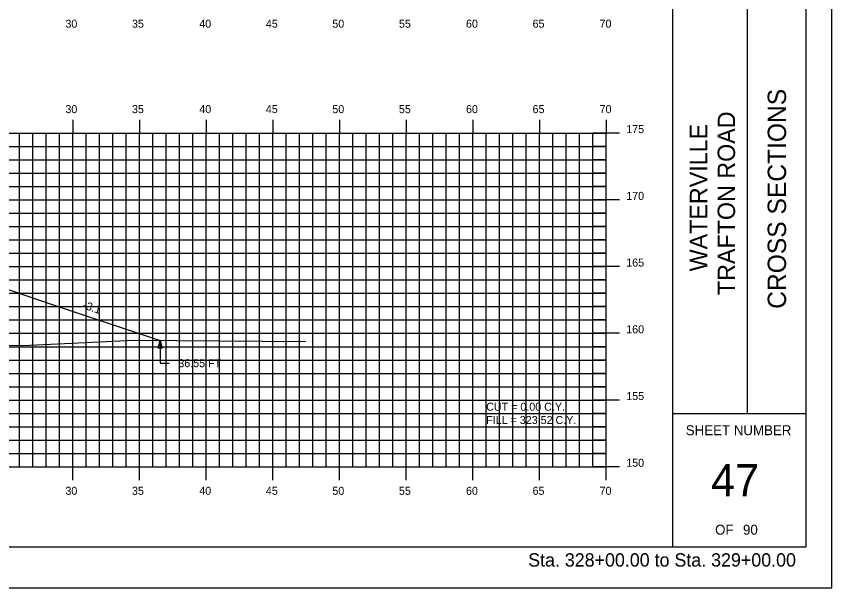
# Model space of a CAD drawing. Extents: x 1140981 to 1141151, y 608981 to 609091.
# Drawn here: x 1141089.5 to 1141150.7, y 608981.3 to 609024.1 of the extents above; entities that cross this region are included whole.
import ezdxf

# ---------------------------------------------------------------- set-up
doc = ezdxf.new("R2010")
doc.units = 0
for name, color, linetype in [('ANNOTATION', 7, 'Continuous'), ('BORDER', 7, 'Continuous'), ('D_Roadway_SlopeLines', 7, 'Continuous'), ('D_Text_Standard', 7, 'Continuous'), ('H_V ANNOTATION', 7, 'Continuous'), ('HIGHWAY_TITLE', 7, 'Continuous'), ('MAJOR', 7, 'Continuous'), ('MINOR', 7, 'Continuous'), ('PLOT BOUNDARY', 7, 'Continuous'), ('S_Roadway_Centerline', 7, 'Continuous')]:
    doc.layers.add(name, color=color, linetype=linetype)

msp = doc.modelspace()

# ---------------------------------------------------------------- linework, layer by layer
msp.add_lwpolyline([(1141028.37, 608999.408), (1141037.741, 609002.532), (1141040.741, 609003.532), (1141048.445, 609006.1), (1141048.446, 609006.1), (1141052.758, 609006.272), (1141063.758, 609006.492), (1141074.758, 609006.272), (1141081.758, 609005.992), (1141089.29, 609003.482), (1141092.29, 609002.482), (1141100.308, 608999.809)])
at = {"layer": 'BORDER'}
for p, q in [((1141138.758, 608984.335), (1141138.758, 609089.335)), ((1141144.349, 608994.338), (1141144.349, 609029.338)), ((1141138.758, 608994.338), (1141148.758, 608994.338))]:
    msp.add_line(p, q, dxfattribs=at)
msp.add_lwpolyline([(1140988.758, 608984.335), (1141148.758, 608984.335), (1141148.758, 609089.335), (1140988.758, 609089.335)], close=True, dxfattribs=at)
at = {"layer": 'D_Roadway_SlopeLines'}
for points in [[(1141089.29, 609003.482), (1141092.29, 609002.482)], [(1141092.29, 609002.482), (1141100.308, 608999.809)]]:
    msp.add_lwpolyline(points, dxfattribs=at)
at = {"layer": 'D_Text_Standard'}
msp.add_lwpolyline([(1141100.308, 608999.809), (1141100.455, 608999.227), (1141100.164, 608999.226)], close=True, dxfattribs=at)
msp.add_lwpolyline([(1141100.308, 608999.809), (1141100.312, 608998.097), (1141100.992, 608998.097)], dxfattribs=at)
at = {"layer": 'MAJOR'}
for p, q in [((1141093.758, 609016.337), (1141093.758, 609015.335)), ((1141098.758, 609016.337), (1141098.758, 609015.335)), ((1141103.758, 609016.337), (1141103.758, 609015.335)), ((1141108.758, 609016.337), (1141108.758, 609015.335)), ((1141113.758, 609016.337), (1141113.758, 609015.335)), ((1141118.758, 609016.337), (1141118.758, 609015.335)), ((1141123.758, 609016.337), (1141123.758, 609015.335)), ((1141128.758, 609016.337), (1141128.758, 609015.335)), ((1141133.758, 609016.337), (1141133.758, 609015.335)), ((1140993.758, 609015.335), (1141133.758, 609015.335)), ((1140993.758, 609015.335), (1141133.758, 609015.335)), ((1141093.758, 608990.335), (1141093.758, 609015.335)), ((1141098.758, 608990.335), (1141098.758, 609015.335)), ((1141103.758, 608990.335), (1141103.758, 609015.335)), ((1141108.758, 608990.335), (1141108.758, 609015.335)), ((1141113.758, 608990.335), (1141113.758, 609015.335)), ((1141118.758, 608990.335), (1141118.758, 609015.335)), ((1141123.758, 608990.335), (1141123.758, 609015.335)), ((1141128.758, 608990.335), (1141128.758, 609015.335)), ((1141134.76, 609015.335), (1141132.756, 609015.335)), ((1141133.758, 608990.335), (1141133.758, 609015.335)), ((1141133.758, 608990.335), (1141133.758, 609015.335)), ((1140993.758, 609010.335), (1141133.758, 609010.335)), ((1141134.76, 609010.335), (1141132.756, 609010.335)), ((1140993.758, 609005.335), (1141133.758, 609005.335)), ((1141134.76, 609005.335), (1141132.756, 609005.335)), ((1140993.758, 609000.335), (1141133.758, 609000.335)), ((1141134.76, 609000.335), (1141132.756, 609000.335)), ((1140993.758, 608995.335), (1141133.758, 608995.335)), ((1141134.76, 608995.335), (1141132.756, 608995.335)), ((1140993.758, 608990.335), (1141133.758, 608990.335)), ((1140993.758, 608990.335), (1141133.758, 608990.335)), ((1141093.758, 608989.333), (1141093.758, 608990.335)), ((1141098.758, 608989.333), (1141098.758, 608990.335)), ((1141103.758, 608989.333), (1141103.758, 608990.335)), ((1141108.758, 608989.333), (1141108.758, 608990.335)), ((1141113.758, 608989.333), (1141113.758, 608990.335)), ((1141118.758, 608989.333), (1141118.758, 608990.335)), ((1141123.758, 608989.333), (1141123.758, 608990.335)), ((1141128.758, 608989.333), (1141128.758, 608990.335)), ((1141134.76, 608990.335), (1141132.756, 608990.335)), ((1141133.758, 608989.333), (1141133.758, 608990.335))]:
    msp.add_line(p, q, dxfattribs=at)
at = {"layer": 'MINOR'}
for p, q in [((1141089.758, 608990.335), (1141089.758, 609015.335)), ((1141090.758, 608990.335), (1141090.758, 609015.335)), ((1141091.758, 608990.335), (1141091.758, 609015.335)), ((1141092.758, 608990.335), (1141092.758, 609015.335)), ((1141094.758, 608990.335), (1141094.758, 609015.335)), ((1141095.758, 608990.335), (1141095.758, 609015.335)), ((1141096.758, 608990.335), (1141096.758, 609015.335)), ((1141097.758, 608990.335), (1141097.758, 609015.335)), ((1141099.758, 608990.335), (1141099.758, 609015.335)), ((1141100.758, 608990.335), (1141100.758, 609015.335)), ((1141101.758, 608990.335), (1141101.758, 609015.335)), ((1141102.758, 608990.335), (1141102.758, 609015.335)), ((1141104.758, 608990.335), (1141104.758, 609015.335)), ((1141105.758, 608990.335), (1141105.758, 609015.335)), ((1141106.758, 608990.335), (1141106.758, 609015.335)), ((1141107.758, 608990.335), (1141107.758, 609015.335)), ((1141109.758, 608990.335), (1141109.758, 609015.335)), ((1141110.758, 608990.335), (1141110.758, 609015.335)), ((1141111.758, 608990.335), (1141111.758, 609015.335)), ((1141112.758, 608990.335), (1141112.758, 609015.335)), ((1141114.758, 608990.335), (1141114.758, 609015.335)), ((1141115.758, 608990.335), (1141115.758, 609015.335)), ((1141116.758, 608990.335), (1141116.758, 609015.335)), ((1141117.758, 608990.335), (1141117.758, 609015.335)), ((1141119.758, 608990.335), (1141119.758, 609015.335)), ((1141120.758, 608990.335), (1141120.758, 609015.335)), ((1141121.758, 608990.335), (1141121.758, 609015.335)), ((1141122.758, 608990.335), (1141122.758, 609015.335)), ((1141124.758, 608990.335), (1141124.758, 609015.335)), ((1141125.758, 608990.335), (1141125.758, 609015.335)), ((1141126.758, 608990.335), (1141126.758, 609015.335)), ((1141127.758, 608990.335), (1141127.758, 609015.335)), ((1141129.758, 608990.335), (1141129.758, 609015.335)), ((1141130.758, 608990.335), (1141130.758, 609015.335)), ((1141131.758, 608990.335), (1141131.758, 609015.335)), ((1141132.758, 608990.335), (1141132.758, 609015.335)), ((1140993.758, 609014.335), (1141133.758, 609014.335)), ((1141133.758, 609014.335), (1141132.756, 609014.335)), ((1140993.758, 609013.335), (1141133.758, 609013.335)), ((1141133.758, 609013.335), (1141132.756, 609013.335)), ((1140993.758, 609012.335), (1141133.758, 609012.335)), ((1141133.758, 609012.335), (1141132.756, 609012.335)), ((1140993.758, 609011.335), (1141133.758, 609011.335)), ((1141133.758, 609011.335), (1141132.756, 609011.335)), ((1140993.758, 609009.335), (1141133.758, 609009.335)), ((1141133.758, 609009.335), (1141132.756, 609009.335)), ((1140993.758, 609008.335), (1141133.758, 609008.335)), ((1141133.758, 609008.335), (1141132.756, 609008.335)), ((1140993.758, 609007.335), (1141133.758, 609007.335)), ((1141133.758, 609007.335), (1141132.756, 609007.335)), ((1140993.758, 609006.335), (1141133.758, 609006.335)), ((1141133.758, 609006.335), (1141132.756, 609006.335)), ((1140993.758, 609004.335), (1141133.758, 609004.335)), ((1141133.758, 609004.335), (1141132.756, 609004.335)), ((1140993.758, 609003.335), (1141133.758, 609003.335)), ((1141133.758, 609003.335), (1141132.756, 609003.335)), ((1140993.758, 609002.335), (1141133.758, 609002.335)), ((1141133.758, 609002.335), (1141132.756, 609002.335)), ((1140993.758, 609001.335), (1141133.758, 609001.335)), ((1141133.758, 609001.335), (1141132.756, 609001.335)), ((1140993.758, 608999.335), (1141133.758, 608999.335)), ((1141133.758, 608999.335), (1141132.756, 608999.335)), ((1140993.758, 608998.335), (1141133.758, 608998.335)), ((1141133.758, 608998.335), (1141132.756, 608998.335)), ((1140993.758, 608997.335), (1141133.758, 608997.335)), ((1141133.758, 608997.335), (1141132.756, 608997.335)), ((1140993.758, 608996.335), (1141133.758, 608996.335)), ((1141133.758, 608996.335), (1141132.756, 608996.335)), ((1140993.758, 608994.335), (1141133.758, 608994.335)), ((1141133.758, 608994.335), (1141132.756, 608994.335)), ((1140993.758, 608993.335), (1141133.758, 608993.335)), ((1141133.758, 608993.335), (1141132.756, 608993.335)), ((1140993.758, 608992.335), (1141133.758, 608992.335)), ((1141133.758, 608992.335), (1141132.756, 608992.335)), ((1140993.758, 608991.335), (1141133.758, 608991.335)), ((1141133.758, 608991.335), (1141132.756, 608991.335))]:
    msp.add_line(p, q, dxfattribs=at)
at = {"layer": 'PLOT BOUNDARY'}
msp.add_lwpolyline([(1140980.664, 608981.276), (1141150.664, 608981.276), (1141150.664, 609091.276), (1140980.664, 609091.276)], close=True, dxfattribs=at)
at = {"layer": 'S_Roadway_Centerline'}
msp.add_lwpolyline([(1141027.789, 608999.416), (1141035.022, 608999.326), (1141040.825, 608999.303), (1141045.714, 608999.441), (1141048.189, 609000.255), (1141049.547, 609000.562), (1141050.711, 609000.691), (1141052.407, 609000.823), (1141057.263, 609000.985), (1141063.484, 609001.223), (1141069.357, 609001.03), (1141074.221, 609000.94), (1141075.625, 609000.829), (1141077.818, 609000.611), (1141079.61, 609000.29), (1141081.915, 608999.63), (1141085.352, 608999.529), (1141090.008, 608999.43), (1141098.326, 608999.824), (1141111.196, 608999.728)], dxfattribs=at)

# ---------------------------------------------------------------- texts
at = {"layer": 'ANNOTATION'}
msp.add_text('-3:1', height=0.6, rotation=341.56505, dxfattribs=at).set_placement((1141094.449, 609002.216))
at = {"layer": 'BORDER'}
msp.add_text('CROSS SECTIONS', height=1.37787, rotation=90, dxfattribs=at).set_placement((1141147.242, 609002.172))
for s, height, p in [('SHEET NUMBER', 0.74527, (1141139.723, 608992.701)), ('47', 2.4194, (1141141.619, 608988.118)), ('OF', 0.7453, (1141141.925, 608985.248)), ('90', 0.7453, (1141144.014, 608985.248))]:
    msp.add_text(s, height=height, dxfattribs=at).set_placement(p)
at = {"layer": 'D_Text_Standard'}
for s, p in [('36.55 FT', (1141101.672, 608997.797)), ('CUT = 0.00 C.Y.', (1141124.758, 608994.535)), ('FILL = 323.52 C.Y.', (1141124.758, 608993.539))]:
    msp.add_text(s, height=0.6, dxfattribs=at).set_placement(p)
at = {"layer": 'H_V ANNOTATION'}
for s, height, p in [('30', 0.6, (1141093.206, 609023.235)), ('35', 0.6, (1141098.198, 609023.235)), ('40', 0.6, (1141103.244, 609023.235)), ('45', 0.6, (1141108.236, 609023.235)), ('50', 0.6, (1141113.222, 609023.235)), ('55', 0.6, (1141118.214, 609023.235)), ('60', 0.6, (1141123.244, 609023.235)), ('65', 0.6, (1141128.236, 609023.235)), ('70', 0.6, (1141133.26, 609023.235)), ('30', 0.6, (1141093.206, 609016.835)), ('35', 0.6, (1141098.198, 609016.835)), ('40', 0.6, (1141103.244, 609016.835)), ('45', 0.6, (1141108.236, 609016.835)), ('50', 0.6, (1141113.222, 609016.835)), ('55', 0.6, (1141118.214, 609016.835)), ('60', 0.6, (1141123.244, 609016.835)), ('65', 0.6, (1141128.236, 609016.835)), ('70', 0.6, (1141133.26, 609016.835)), ('175', 0.6, (1141135.258, 609015.335)), ('170', 0.6, (1141135.258, 609010.335)), ('165', 0.6, (1141135.258, 609005.335)), ('160', 0.6, (1141135.258, 609000.335)), ('155', 0.6, (1141135.258, 608995.335)), ('150', 0.6, (1141135.258, 608990.335)), ('30', 0.6, (1141093.206, 608988.235)), ('35', 0.6, (1141098.198, 608988.235)), ('40', 0.6, (1141103.244, 608988.235)), ('45', 0.6, (1141108.236, 608988.235)), ('50', 0.6, (1141113.222, 608988.235)), ('55', 0.6, (1141118.214, 608988.235)), ('60', 0.6, (1141123.244, 608988.235)), ('65', 0.6, (1141128.236, 608988.235)), ('70', 0.6, (1141133.26, 608988.235)), ('Sta. 328+00.00 to Sta. 329+00.00', 1.0002, (1141127.904, 608982.855))]:
    msp.add_text(s, height=height, dxfattribs=at).set_placement(p)
at = {"layer": 'HIGHWAY_TITLE'}
for s, height, p in [('TRAFTON ROAD', 1.30428, (1141143.417, 609003.201)), ('WATERVILLE', 1.3043, (1141141.33, 609004.98))]:
    msp.add_text(s, height=height, rotation=90, dxfattribs=at).set_placement(p)

doc.saveas('drawing.dxf')
